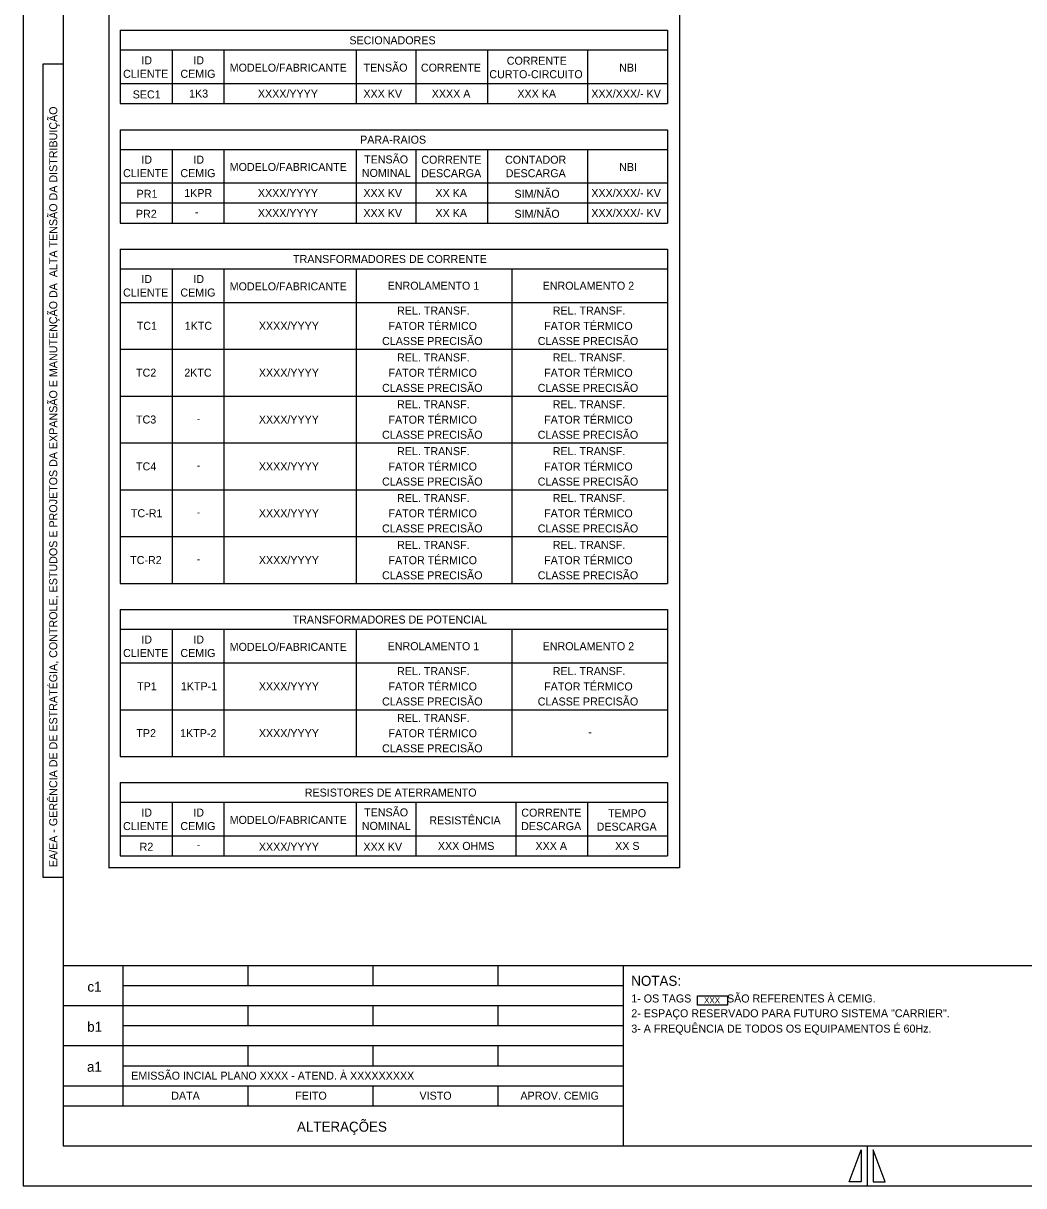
# Model space of a CAD drawing. Extents: x 563 to 1404, y 358 to 952.
# Drawn here: x 562.6 to 812.7, y 358 to 648.4 of the extents above; entities that cross this region are included whole.
import ezdxf

# ---------------------------------------------------------------- set-up
doc = ezdxf.new("R2010")
doc.units = 0
doc.layers.add('New Level (0)', color=7, linetype='Continuous')

# ---------------------------------------------------------------- blocks, each defined once
blk = doc.blocks.new('POINT_DISPLAY')
blk.add_line((0, 0), (0, 0))

msp = doc.modelspace()

# ---------------------------------------------------------------- linework, layer by layer
at = {"layer": 'New Level (0)'}
for p, q in [((562.58, 951.96), (562.58, 357.96)), ((562.58, 951.96), (562.58, 357.96)), ((572.58, 941.96), (572.58, 367.96)), ((572.58, 941.96), (572.58, 367.96)), ((583.96, 679.5), (583.96, 437.32)), ((726.65, 679.5), (726.65, 437.37)), ((586.81, 646.67), (586.81, 628.34)), ((586.81, 646.67), (723.65, 646.67)), ((723.65, 646.67), (723.65, 628.34)), ((723.65, 641.67), (586.81, 641.67)), ((599.81, 641.67), (599.81, 628.34)), ((612.81, 628.34), (612.81, 641.67)), ((645.81, 641.67), (645.81, 628.34)), ((660.72, 641.67), (660.72, 628.34)), ((678.66, 641.67), (678.66, 628.34)), ((703.66, 641.67), (703.66, 628.34)), ((567.58, 638.29), (572.58, 638.29)), ((567.58, 434.97), (567.58, 638.29)), ((586.81, 633.34), (723.65, 633.34)), ((586.81, 628.34), (723.65, 628.34)), ((586.81, 628.34), (723.65, 628.34)), ((586.81, 621.84), (586.81, 598.52)), ((586.81, 621.84), (723.65, 621.84)), ((723.65, 621.84), (723.65, 598.52)), ((723.65, 616.84), (586.81, 616.84)), ((599.81, 616.84), (599.81, 598.52)), ((612.81, 598.52), (612.81, 616.84)), ((645.81, 616.84), (645.81, 598.52)), ((660.72, 616.84), (660.72, 598.52)), ((678.66, 616.84), (678.66, 598.52)), ((703.66, 616.84), (703.66, 598.52)), ((586.81, 608.52), (723.65, 608.52)), ((629.06, 608.52), (723.65, 608.52)), ((586.81, 603.52), (723.65, 603.52)), ((586.81, 598.52), (723.65, 598.52)), ((586.81, 592.02), (586.81, 508.44)), ((586.81, 592.02), (723.65, 592.02)), ((723.65, 592.02), (723.65, 508.44)), ((723.65, 587.02), (586.81, 587.02)), ((599.81, 587.02), (599.81, 508.44)), ((612.81, 508.44), (612.81, 587.02)), ((645.81, 587.02), (645.81, 508.44)), ((684.73, 587.02), (684.73, 508.44)), ((586.81, 578.69), (723.65, 578.69)), ((586.81, 566.98), (723.65, 566.98)), ((586.81, 555.27), (723.65, 555.27)), ((586.81, 543.57), (723.65, 543.57)), ((586.81, 531.86), (723.65, 531.86)), ((586.81, 520.15), (723.65, 520.15)), ((586.81, 508.44), (723.65, 508.44)), ((586.81, 508.44), (586.81, 508.44)), ((586.81, 508.44), (586.81, 508.44)), ((586.81, 501.94), (586.81, 465.2)), ((586.81, 501.94), (723.65, 501.94)), ((723.65, 501.94), (723.65, 465.2)), ((723.65, 496.94), (586.81, 496.94)), ((599.81, 496.94), (599.81, 465.2)), ((612.81, 465.2), (612.81, 496.94)), ((645.81, 496.94), (645.81, 465.2)), ((684.73, 496.94), (684.73, 465.2)), ((586.81, 488.61), (723.65, 488.61)), ((586.81, 476.91), (723.65, 476.91)), ((586.81, 465.2), (723.65, 465.2)), ((586.81, 458.7), (586.81, 440.37)), ((586.81, 458.7), (723.65, 458.7)), ((723.65, 458.7), (723.65, 440.37)), ((723.65, 453.7), (586.81, 453.7)), ((599.81, 453.7), (599.81, 440.37)), ((612.81, 440.37), (612.81, 453.7)), ((645.81, 453.7), (645.81, 440.37)), ((660.72, 453.7), (660.72, 440.37)), ((685.72, 453.7), (685.72, 440.37)), ((703.66, 453.7), (703.66, 440.37)), ((703.66, 453.7), (703.66, 440.37)), ((586.81, 445.37), (723.65, 445.37)), ((629.06, 445.37), (723.65, 445.37)), ((586.81, 440.37), (723.65, 440.37)), ((726.65, 437.37), (583.96, 437.37)), ((572.58, 434.97), (567.58, 434.97)), ((572.58, 412.96), (1393.58, 412.96)), ((587.58, 377.96), (587.58, 412.96)), ((618.83, 407.96), (618.83, 412.96)), ((650.08, 407.96), (650.08, 412.96)), ((681.33, 407.96), (681.33, 412.96)), ((712.58, 412.96), (712.58, 367.96)), ((587.58, 407.96), (712.58, 407.96)), ((572.58, 402.96), (712.58, 402.96)), ((618.83, 397.96), (618.83, 402.96)), ((650.08, 397.96), (650.08, 402.96)), ((681.33, 397.96), (681.33, 402.96)), ((587.58, 397.96), (712.58, 397.96)), ((572.58, 392.96), (712.58, 392.96)), ((618.83, 387.96), (618.83, 392.96)), ((650.08, 387.96), (650.08, 392.96)), ((681.33, 387.96), (681.33, 392.96)), ((587.58, 387.96), (712.58, 387.96)), ((572.58, 382.96), (712.58, 382.96)), ((618.83, 377.96), (618.83, 382.96)), ((650.08, 377.96), (650.08, 382.96)), ((681.33, 377.96), (681.33, 382.96)), ((572.58, 377.96), (712.58, 377.96)), ((572.58, 367.96), (1393.58, 367.96)), ((572.58, 367.96), (1393.58, 367.96)), ((769.08, 358.96), (772.08, 366.96)), ((772.08, 366.96), (772.08, 358.96)), ((773.58, 367.96), (773.58, 357.96)), ((775.08, 366.96), (775.08, 358.96)), ((778.08, 358.96), (775.08, 366.96)), ((562.58, 357.96), (1403.58, 357.96)), ((562.58, 357.96), (1403.58, 357.96)), ((772.08, 358.96), (769.08, 358.96)), ((775.08, 358.96), (778.08, 358.96))]:
    msp.add_line(p, q, dxfattribs=at)
msp.add_lwpolyline([(731.16, 405.44), (738.67, 405.44), (738.67, 403.1), (731.16, 403.1)], close=True, dxfattribs=at)

# ---------------------------------------------------------------- block references
for p in [(655.23, 578.69), (655.23, 488.61)]:
    msp.add_blockref('POINT_DISPLAY', p, dxfattribs=at)

# ---------------------------------------------------------------- texts
for s, height, p in [('SECIONADORES', 2, (644.11, 643.17)), ('ID', 2, (592.1, 638.17)), ('ID', 2, (605.1, 638.17)), ('CORRENTE', 2, (683.46, 638.07)), ('CLIENTE', 2, (587.54, 634.8)), ('CEMIG', 2, (601.87, 634.8)), ('MODELO/FABRICANTE', 2, (614.19, 636.34)), ('TENSÃO', 2, (647.65, 636.34)), ('CORRENTE', 2, (661.99, 636.34)), ('CURTO-CIRCUITO', 2, (679.1, 634.7)), ('NBI', 2, (711.56, 636.34)), ('SEC1', 2, (589.94, 629.65)), ('1K3', 2, (604.04, 629.86)), ('XXXX/YYYY', 2, (621.24, 629.84)), ('XXX KV', 2, (647.62, 629.84)), ('XXXX A', 2, (664.7, 629.84)), ('XXX KA', 2, (686.11, 629.84)), ('XXX/XXX/- KV', 2, (704.59, 629.84)), ('PARA-RAIOS', 2, (646.79, 618.34)), ('TENSÃO ', 2, (647.79, 613.4)), ('ID', 2, (592.1, 613.34)), ('ID', 2, (605.1, 613.34)), ('MODELO/FABRICANTE', 2, (614.19, 611.52)), ('CORRENTE', 2, (662.09, 613.33)), ('CONTADOR', 2, (683.02, 613.33)), ('NBI', 2, (711.56, 611.52)), ('CLIENTE', 2, (587.54, 609.98)), ('CEMIG', 2, (601.87, 609.98)), ('NOMINAL', 2, (647.23, 610.03)), ('DESCARGA', 2, (662.05, 609.96)), ('DESCARGA', 2, (683.19, 609.96)), ('XXXX/YYYY', 2, (621.24, 605.02)), ('SIM/NÃO', 2, (685.38, 604.82)), ('XXX/XXX/- KV', 2, (704.59, 605.02)), ('PR1', 2, (590.92, 604.82)), ('1KPR', 2, (602.83, 605.01)), ('XXX KV', 2, (647.62, 605.02)), ('XX KA', 2, (665.63, 605.02)), ('PR2', 2, (590.74, 599.82)), ('XXXX/YYYY', 2, (621.24, 600.02)), ('XXX KV', 2, (647.62, 600.02)), ('XX KA', 2, (665.63, 600.02)), ('SIM/NÃO', 2, (685.38, 599.82)), ('XXX/XXX/- KV', 2, (704.59, 600.02)), ('-', 2, (605.47, 600.29)), ('TRANSFORMADORES DE CORRENTE', 2, (630.03, 588.52)), ('ID', 2, (592.1, 583.52)), ('ID', 2, (605.1, 583.52)), ('ENROLAMENTO 1', 2, (653.68, 581.85)), ('ENROLAMENTO 2', 2, (692.42, 581.85)), ('CLIENTE', 2, (587.54, 580.15)), ('CEMIG', 2, (601.87, 580.15)), ('MODELO/FABRICANTE', 2, (614.19, 581.69)), ('REL. TRANSF.', 2, (656.03, 575.64)), ('REL. TRANSF.', 2, (694.95, 575.64)), ('TC1', 2, (590.96, 571.83)), ('1KTC', 2, (602.95, 571.83)), ('XXXX/YYYY', 2, (621.48, 571.83)), ('FATOR TÉRMICO', 2, (653.88, 571.8)), ('FATOR TÉRMICO', 2, (692.8, 571.8)), ('CLASSE PRECISÃO', 2, (652.28, 568.03)), ('CLASSE PRECISÃO', 2, (691.2, 568.03)), ('REL. TRANSF.', 2, (656.03, 563.93)), ('REL. TRANSF.', 2, (694.95, 563.93)), ('TC2', 2, (590.78, 560.13)), ('2KTC', 2, (602.84, 560.13)), ('XXXX/YYYY', 2, (621.48, 560.13)), ('FATOR TÉRMICO', 2, (653.88, 560.09)), ('FATOR TÉRMICO', 2, (692.8, 560.09)), ('CLASSE PRECISÃO', 2, (652.28, 556.32)), ('CLASSE PRECISÃO', 2, (691.2, 556.32)), ('REL. TRANSF.', 2, (656.03, 552.22)), ('REL. TRANSF.', 2, (694.95, 552.22)), ('TC3', 2, (590.77, 548.42)), ('-', 2, (605.94, 548.7)), ('XXXX/YYYY', 2, (621.48, 548.42)), ('FATOR TÉRMICO', 2, (653.88, 548.38)), ('FATOR TÉRMICO', 2, (692.8, 548.38)), ('CLASSE PRECISÃO', 2, (652.28, 544.61)), ('CLASSE PRECISÃO', 2, (691.2, 544.61)), ('REL. TRANSF.', 2, (656.03, 540.51)), ('REL. TRANSF.', 2, (694.95, 540.51)), ('TC4', 2, (590.78, 536.71)), ('-', 2, (605.94, 536.99)), ('XXXX/YYYY', 2, (621.48, 536.71)), ('FATOR TÉRMICO', 2, (653.88, 536.67)), ('FATOR TÉRMICO', 2, (692.8, 536.67)), ('CLASSE PRECISÃO', 2, (652.28, 532.91)), ('CLASSE PRECISÃO', 2, (691.2, 532.91)), ('REL. TRANSF.', 2, (656.03, 528.81)), ('REL. TRANSF.', 2, (694.95, 528.81)), ('TC-R1', 2, (589.49, 525)), ('-', 2, (605.94, 525.28)), ('XXXX/YYYY', 2, (621.48, 525)), ('FATOR TÉRMICO', 2, (653.88, 524.97)), ('FATOR TÉRMICO', 2, (692.8, 524.97)), ('CLASSE PRECISÃO', 2, (652.28, 521.2)), ('CLASSE PRECISÃO', 2, (691.2, 521.2)), ('REL. TRANSF.', 2, (656.03, 517.1)), ('REL. TRANSF.', 2, (694.95, 517.1)), ('TC-R2', 2, (589.31, 513.3)), ('-', 2, (605.94, 513.57)), ('XXXX/YYYY', 2, (621.48, 513.3)), ('FATOR TÉRMICO', 2, (653.88, 513.26)), ('FATOR TÉRMICO', 2, (692.8, 513.26)), ('CLASSE PRECISÃO', 2, (652.28, 509.49)), ('CLASSE PRECISÃO', 2, (691.2, 509.49)), ('TRANSFORMADORES DE POTENCIAL', 2, (629.92, 498.44)), ('ID', 2, (592.1, 493.44)), ('ID', 2, (605.1, 493.44)), ('CLIENTE', 2, (587.54, 490.07)), ('CEMIG', 2, (601.87, 490.07)), ('MODELO/FABRICANTE', 2, (614.19, 491.61)), ('ENROLAMENTO 1', 2, (653.68, 491.78)), ('ENROLAMENTO 2', 2, (692.42, 491.78)), ('REL. TRANSF.', 2, (656.03, 485.56)), ('REL. TRANSF.', 2, (694.95, 485.56)), ('TP1', 2, (591.04, 481.76)), ('1KTP-1', 2, (601.99, 481.76)), ('XXXX/YYYY', 2, (621.48, 481.76)), ('FATOR TÉRMICO', 2, (653.88, 481.72)), ('FATOR TÉRMICO', 2, (692.8, 481.72)), ('CLASSE PRECISÃO', 2, (652.28, 477.96)), ('CLASSE PRECISÃO', 2, (691.2, 477.96)), ('REL. TRANSF.', 2, (656.03, 473.86)), ('TP2', 2, (590.86, 470.05)), ('1KTP-2', 2, (601.8, 470.05)), ('XXXX/YYYY', 2, (621.48, 470.05)), ('FATOR TÉRMICO', 2, (653.88, 470.02)), ('-', 2, (703.81, 470.33)), ('CLASSE PRECISÃO', 2, (652.28, 466.25)), ('RESISTORES DE ATERRAMENTO', 2, (632.96, 455.2)), ('ID', 2, (592.1, 450.2)), ('ID', 2, (605.1, 450.2)), ('MODELO/FABRICANTE', 2, (614.19, 448.37)), ('TENSÃO ', 2, (647.79, 450.25)), ('RESISTÊNCIA', 2, (664.09, 448.26)), ('CORRENTE', 2, (687.09, 450.18)), ('TEMPO', 2, (708.78, 450.05)), ('CLIENTE', 2, (587.54, 446.83)), ('CEMIG', 2, (601.87, 446.83)), ('NOMINAL', 2, (647.23, 446.88)), ('DESCARGA', 2, (687.05, 446.81)), ('DESCARGA', 2, (705.92, 446.69)), ('R2', 2, (591.67, 441.67)), ('-', 2, (605.94, 442.15)), ('XXXX/YYYY', 2, (621.48, 441.67)), ('XXX KV', 2, (647.62, 441.67)), ('XXX OHMS', 2, (666.24, 441.87)), ('XXX A', 2, (690.63, 441.87)), ('XX S', 2, (710.55, 441.87)), ('XXX', 1.5, (732.77, 403.54))]:
    msp.add_text(s, height=height).set_placement(p)
msp.add_text('EA/EA - GERÊNCIA DE DE ESTRATÉGIA, CONTROLE, ESTUDOS E PROJETOS DA EXPANSÃO E MANUTENÇÃO DA  ALTA TENSÃO DA DISTRIBUIÇÃO', height=2, rotation=90, dxfattribs=at).set_placement((571.08, 437.56))
for s, height, p in [('NOTAS:', 2.5, (714.58, 407.91)), ('c1', 2.5, (578.62, 406.44)), ('1- OS TAGS            SÃO REFERENTES À CEMIG.', 2, (714.58, 403.75)), ('2- ESPAÇO RESERVADO PARA FUTURO SISTEMA "CARRIER".', 2, (714.58, 400.05)), ('b1', 2.5, (578.57, 396.44)), ('3- A FREQUÊNCIA DE TODOS OS EQUIPAMENTOS É 60Hz.', 2, (714.58, 396.22)), ('a1', 2.5, (578.52, 386.44)), ('EMISSÃO INCIAL PLANO XXXX - ATEND. À XXXXXXXXX', 2, (589.58, 384.46)), ('DATA', 2, (599.58, 379.46)), ('FEITO', 2, (630.58, 379.46)), ('VISTO', 2, (661.64, 379.46)), ('APROV. CEMIG', 2, (686.88, 379.46)), ('ALTERAÇÕES', 2.5, (631.01, 371.46))]:
    msp.add_text(s, height=height, dxfattribs=at).set_placement(p)

doc.saveas('drawing.dxf')
